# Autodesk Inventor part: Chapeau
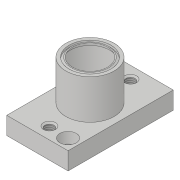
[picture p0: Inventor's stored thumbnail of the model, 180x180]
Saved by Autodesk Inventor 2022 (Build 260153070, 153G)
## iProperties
Created: 2018-06
Part Number: Chapeau
Material: Aluminium 6061
Document SubType Name: Modeling
Designer: Fabian Perrée
Density: 2.7 g/cm^3
Appearance: Générique
Mass: 26.5554 g
Surface Area: 66.9581 cm^2
Volume: 9.83534 cm^3
Author: Fabian Perrée
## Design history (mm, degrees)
sketch "Esquisse1"
  geometry: L1 (-14, 24)-(14, 24); L2 (14, 24)-(14, -24); L3 (14, -24)-(-14, -24); L4 (-14, -24)-(-14, 24); L5 (-14, 24)-(14, -24); L6 (14, 24)-(-14, -24); 1 further point
  constraints: 12 end point, 2 midpoint, 2 parallel, 1 horizontal, 1 perpendicular
  dimensions: "d0" = 28 distance of L2.end L3.end; "d1" = 48 distance of L1.end L2.end
extrude "Extrusion1" new body sketch "Esquisse1" distance "d2" = 8; taper "d3" = 0 deg
sketch "Esquisse2"
  geometry: L1 (0, 0)-(8, 0); L2 (8, -24)-(8, 24) reference; L3 (26, -11)-(26, -9.5); L4 (26, -9.5)-(25, -9.5); L5 (25, -9.5)-(26, -8.5); L6 (26, -8)-(24.268, -9); L7 (24.268, -9)-(8, -9); L8 (8, -9)-(8, -11); L9 (26, -11)-(8, -11); L10 (26, -8.5)-(26, -8); L11 (8, -9)-(2.5, -9); L12 (2.5, -9)-(2.5, -11.5); L13 (2.5, -11.5)-(0, -11.5); L14 (0, 24)-(0, -24) reference; L15 (0, -11.5)-(0, 0); L16 (8, -9)-(8, 0); L17 (8, 0)-(26, 0)
  constraints: 30 end point, 5 point on line, 4 horizontal, 4 perpendicular, 2 collinear, 2 vertical, 1 midpoint
  dimensions: "d4" = 18 distance from line of L2 L17.end; "d5" = 1.5 distance of L3.start L3.end; "d6" = 1 distance of L3.end L4.end; "d7" = 45 deg angle of L4 L5; "d8" = 150 deg angle of L7 L6; "d9" = 22 diameter of L9 L1; "d10" = 16 diameter of L6.start L1; "d11" = 18 diameter of L7 L1; "d12" = 23 diameter of L13 L1; "d13" = 18 diameter of L11 L1; "d14" = 2.5 distance of L12.end L13.end
revolve "Révolution1" stored, may be unused: angle "d15" = 90 deg
revolve "Révolution2" stored, may be unused: angle "d16" = 90 deg
sketch "Esquisse3"
  geometry: L1 (14, -24)-(14, 24) reference; L2 (-14, -24)-(14, -24) reference; L3 (-14, 24)-(-14, -24) reference; L4 (14, 24)-(-14, 24) reference; 3 further points
  dimensions: "d17" = 5 distance from line of L1 point (9, -19); "d18" = 5 distance from line of L2 point (9, -19); "d19" = 5 distance from line of L3 point (-9, 19); "d20" = 5 distance from line of L4 point (-9, 19)
hole "Perçage1" sketch "Esquisse3" at (-9, 19), (9, -19) diameter "d21" = 4.5; stored, may be unused: countersink angle "d25" = 90 deg, drill point angle "d27" = 118 deg; dims "d22" = 6, "d23" = 7.5, "d24" = 5, "d26" = 8
sketch "Esquisse4"
  geometry: L1 (-14, 24)-(-14, -24) reference; L2 (-14, -24)-(14, -24) reference; L3 (14, 24)-(-14, 24) reference; 4 further points
  constraints: 2 vertical alignment, 1 midpoint
  dimensions: "d29" = 5.5 distance from line of L2 point (0, -18.5) (= d31); "d31" = 5.5 distance from line of L3 point (0, 18.5)
hole "Perçage2" sketch "Esquisse4" at (0, -18.5), (0, 18.5) diameter "d32" = 4.134; stored, may be unused: countersink angle "d36" = 90 deg, drill point angle "d38" = 118 deg; dims "d33" = 10, "d34" = 5.5, "d35" = 5, "d37" = 14.2
feature "Scission1"
node "Solide1"
